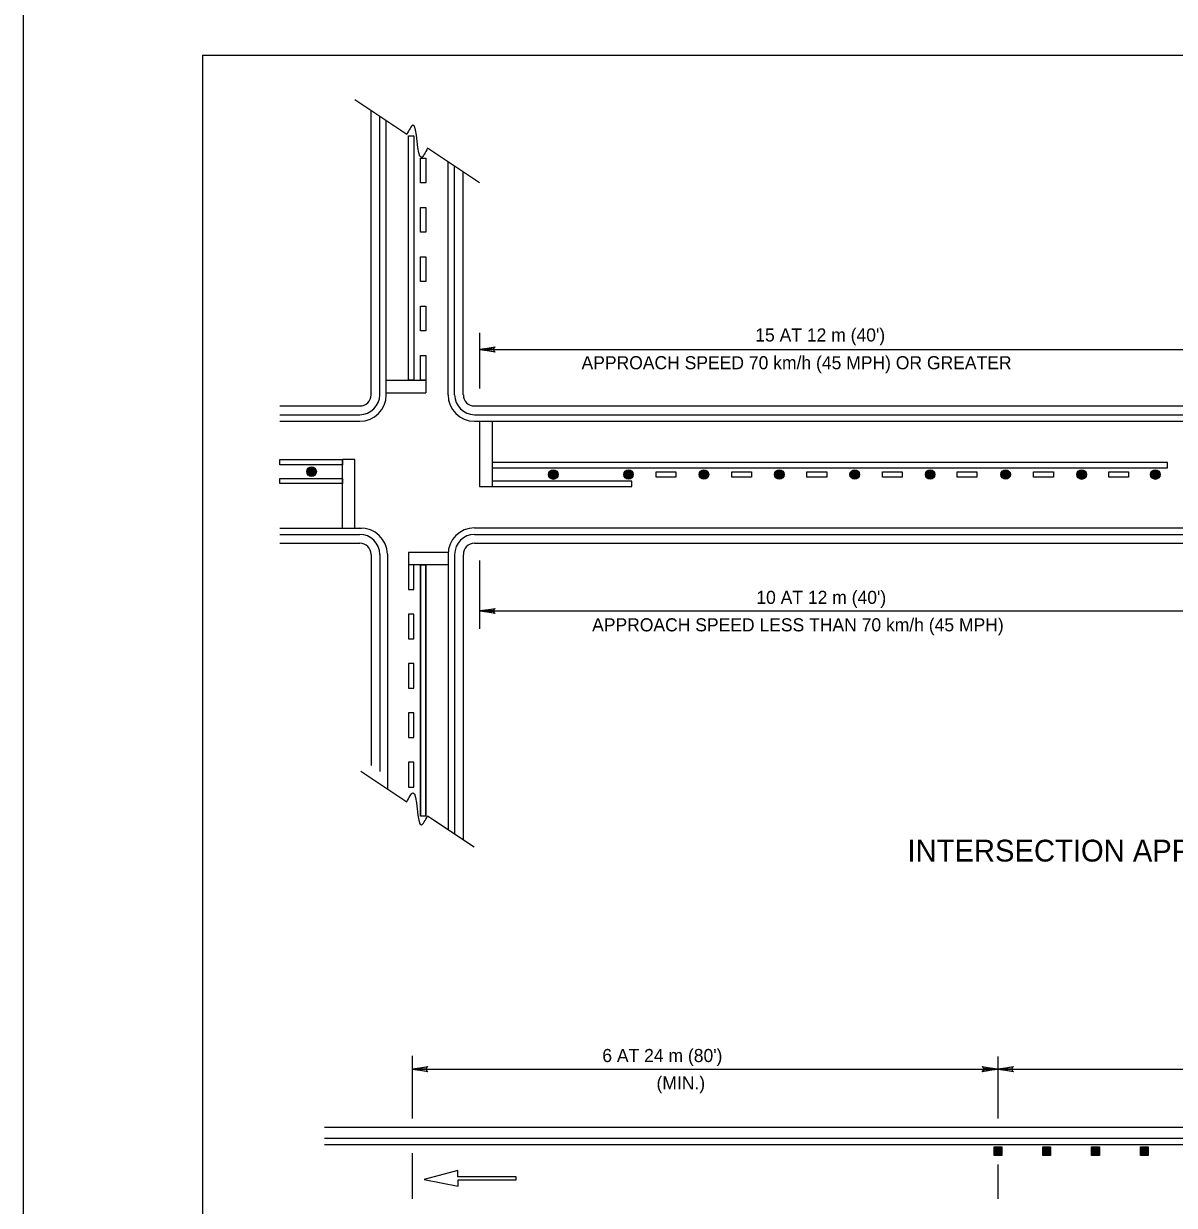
# Model space of a CAD drawing. Extents: x 639362 to 641108, y 298458 to 299646.
# Drawn here: x 639362.3 to 639626, y 298773.7 to 299044.4 of the extents above; entities that cross this region are included whole.
import ezdxf

# ---------------------------------------------------------------- set-up
doc = ezdxf.new("R2010")
doc.units = 0
for name, color, linetype in [('1', 7, 'Continuous'), ('2', 7, 'Continuous'), ('3', 7, 'Continuous'), ('PLT-BNDY', 7, 'Continuous')]:
    doc.layers.add(name, color=color, linetype=linetype)

# ---------------------------------------------------------------- blocks, each defined once
blk = doc.blocks.new('RARROW')
at = {"layer": '3'}
blk.add_lwpolyline([(-2.2695, 0.285), (-2.184875, 0.12075), (0, 0), (-2.2695, 0.285), (-2.38575, 0.384625), (0, 0), (-2.183125, -0.108), (-2.262875, -0.2705), (0, 0), (-2.38575, -0.379125), (-2.262875, -0.2705)], dxfattribs=at)

msp = doc.modelspace()

# ---------------------------------------------------------------- linework, layer by layer
at = {"layer": '1'}
for q in [(640189.27, 299037.19), (639403.27, 298473.19)]:
    msp.add_line((639403.27, 299037.19), q, dxfattribs=at)
at = {"layer": '2'}
for p, q in [((639450.1, 299019.03), (639438.22, 299026.95)), ((639441.9, 298959.38), (639441.9, 299024.5)), ((639443.9, 298959.38), (639443.9, 299023.16)), ((639445.4, 298959.38), (639445.4, 299022.16)), ((639450.51, 298962.69), (639450.51, 299018.73)), ((639450.51, 299018.73), (639451.71, 299018.73)), ((639451.71, 299018.73), (639451.71, 298962.69)), ((639466.76, 299007.92), (639454.86, 299015.86)), ((639459.55, 298959.38), (639459.55, 299012.73)), ((639461.05, 298959.38), (639461.05, 299011.73)), ((639463.05, 298959.38), (639463.05, 299010.4)), ((639466.77, 298973.53), (639466.77, 298960.81)), ((639466.77, 298969.77), (639638.59, 298969.77)), ((639445.4, 298962.69), (639454.45, 298962.69)), ((639451.71, 298962.69), (639450.51, 298962.69)), ((639454.45, 298962.7), (639454.45, 298959.83)), ((639445.4, 298959.83), (639454.45, 298959.83)), ((639421.03, 298956.81), (639439.33, 298956.81)), ((639421.03, 298954.81), (639439.33, 298954.81)), ((639465.63, 298956.81), (639777.38, 298956.81)), ((639465.63, 298954.81), (639777.38, 298954.81)), ((639421.03, 298953.31), (639439.33, 298953.31)), ((639465.63, 298953.31), (639777.38, 298953.31)), ((639466.78, 298953.31), (639466.78, 298938.35)), ((639469.64, 298953.31), (639469.64, 298938.35)), ((639438.18, 298944.52), (639435.33, 298944.52)), ((639435.33, 298928.83), (639435.33, 298944.52)), ((639438.18, 298928.83), (639438.18, 298944.52)), ((639624.41, 298943.86), (639469.63, 298943.86)), ((639469.63, 298943.86), (639469.63, 298942.66)), ((639624.41, 298942.66), (639624.41, 298943.86)), ((639469.63, 298942.66), (639624.41, 298942.66)), ((639466.78, 298938.35), (639469.64, 298938.35)), ((639501.67, 298939.55), (639469.64, 298939.55)), ((639469.64, 298939.55), (639469.64, 298938.35)), ((639469.64, 298938.35), (639501.67, 298938.35)), ((639501.67, 298938.35), (639501.67, 298939.55)), ((639421.03, 298928.83), (639439.69, 298928.83)), ((639421.03, 298927.38), (639439.33, 298927.38)), ((639465.63, 298928.88), (639777.38, 298928.88)), ((639465.63, 298927.38), (639777.38, 298927.38)), ((639421.03, 298925.38), (639439.33, 298925.38)), ((639465.63, 298925.38), (639777.38, 298925.38)), ((639441.9, 298922.81), (639441.9, 298874.4)), ((639443.9, 298922.81), (639443.9, 298873.07)), ((639445.69, 298922.83), (639445.69, 298869.02)), ((639450.51, 298923.24), (639450.51, 298920.39)), ((639459.57, 298923.24), (639450.51, 298923.24)), ((639459.55, 298922.81), (639459.55, 298859.78)), ((639461.05, 298922.81), (639461.05, 298858.78)), ((639463.05, 298922.81), (639463.05, 298857.44)), ((639459.55, 298920.39), (639450.51, 298920.39)), ((639454.45, 298920.39), (639453.25, 298920.39)), ((639453.25, 298920.39), (639453.25, 298862.84)), ((639453.25, 298862.84), (639453.25, 298920.39)), ((639453.25, 298920.39), (639454.45, 298920.39)), ((639454.45, 298862.84), (639454.45, 298920.39)), ((639454.45, 298920.39), (639454.45, 298862.84)), ((639466.77, 298921.38), (639466.77, 298905.73)), ((639466.77, 298909.84), (639638.59, 298909.84)), ((639439.54, 298873.12), (639450.1, 298866.08)), ((639454.45, 298862.84), (639453.25, 298862.84)), ((639454.86, 298862.91), (639465.53, 298855.8)), ((639451.32, 298807.88), (639451.32, 298793.58)), ((639585.52, 298807.8), (639585.52, 298793.58)), ((639451.32, 298804.88), (639585.52, 298804.88)), ((639585.52, 298804.88), (639797.99, 298804.88)), ((639431.25, 298791.58), (639952.64, 298791.58)), ((639431.25, 298789.08), (639952.64, 298789.08)), ((639431.25, 298787.58), (639952.64, 298787.58)), ((639584.64, 298787.09), (639586.41, 298787.09)), ((639584.64, 298785.05), (639584.64, 298787.09)), ((639584.81, 298786.92), (639586.23, 298786.92)), ((639584.81, 298785.23), (639584.81, 298786.92)), ((639584.99, 298786.74), (639586.06, 298786.74)), ((639584.99, 298785.41), (639584.99, 298786.74)), ((639585.17, 298785.59), (639585.17, 298786.56)), ((639585.17, 298786.56), (639585.88, 298786.56)), ((639585.88, 298786.56), (639585.88, 298785.59)), ((639586.06, 298786.74), (639586.06, 298785.41)), ((639586.23, 298786.92), (639586.23, 298785.23)), ((639586.41, 298787.09), (639586.41, 298785.05)), ((639595.82, 298787.09), (639597.59, 298787.09)), ((639595.82, 298785.05), (639595.82, 298787.09)), ((639596, 298786.92), (639597.42, 298786.92)), ((639596, 298785.23), (639596, 298786.92)), ((639596.17, 298786.74), (639597.24, 298786.74)), ((639596.17, 298785.41), (639596.17, 298786.74)), ((639596.35, 298785.59), (639596.35, 298786.56)), ((639596.35, 298786.56), (639597.06, 298786.56)), ((639597.06, 298786.56), (639597.06, 298785.59)), ((639597.24, 298786.74), (639597.24, 298785.41)), ((639597.42, 298786.92), (639597.42, 298785.23)), ((639597.59, 298787.09), (639597.59, 298785.05)), ((639607, 298787.09), (639608.78, 298787.09)), ((639607, 298785.05), (639607, 298787.09)), ((639607.18, 298786.92), (639608.6, 298786.92)), ((639607.18, 298785.23), (639607.18, 298786.92)), ((639607.36, 298786.74), (639608.42, 298786.74)), ((639607.36, 298785.41), (639607.36, 298786.74)), ((639607.54, 298785.59), (639607.54, 298786.56)), ((639607.54, 298786.56), (639608.24, 298786.56)), ((639608.24, 298786.56), (639608.24, 298785.59)), ((639608.42, 298786.74), (639608.42, 298785.41)), ((639608.6, 298786.92), (639608.6, 298785.23)), ((639608.78, 298787.09), (639608.78, 298785.05)), ((639618.19, 298787.09), (639619.96, 298787.09)), ((639618.19, 298785.05), (639618.19, 298787.09)), ((639618.36, 298786.92), (639619.78, 298786.92)), ((639618.36, 298785.23), (639618.36, 298786.92)), ((639618.54, 298786.74), (639619.61, 298786.74)), ((639618.54, 298785.41), (639618.54, 298786.74)), ((639618.72, 298785.59), (639618.72, 298786.56)), ((639618.72, 298786.56), (639619.43, 298786.56)), ((639619.43, 298786.56), (639619.43, 298785.59)), ((639619.61, 298786.74), (639619.61, 298785.41)), ((639619.78, 298786.92), (639619.78, 298785.23)), ((639619.96, 298787.09), (639619.96, 298785.05)), ((639451.32, 298785.58), (639451.32, 298775.16)), ((639586.41, 298785.05), (639584.64, 298785.05)), ((639586.23, 298785.23), (639584.81, 298785.23)), ((639586.06, 298785.41), (639584.99, 298785.41)), ((639585.88, 298785.59), (639585.17, 298785.59)), ((639585.35, 298786.39), (639585.7, 298786.39)), ((639585.35, 298785.76), (639585.35, 298786.39)), ((639585.7, 298785.76), (639585.35, 298785.76)), ((639585.52, 298786.21), (639585.52, 298785.94)), ((639585.7, 298786.39), (639585.7, 298785.76)), ((639597.59, 298785.05), (639595.82, 298785.05)), ((639597.42, 298785.23), (639596, 298785.23)), ((639597.24, 298785.41), (639596.17, 298785.41)), ((639597.06, 298785.59), (639596.35, 298785.59)), ((639596.53, 298786.39), (639596.88, 298786.39)), ((639596.53, 298785.76), (639596.53, 298786.39)), ((639596.88, 298785.76), (639596.53, 298785.76)), ((639596.7, 298786.21), (639596.7, 298785.94)), ((639596.88, 298786.39), (639596.88, 298785.76)), ((639608.78, 298785.05), (639607, 298785.05)), ((639608.6, 298785.23), (639607.18, 298785.23)), ((639608.42, 298785.41), (639607.36, 298785.41)), ((639608.24, 298785.59), (639607.54, 298785.59)), ((639607.71, 298786.39), (639608.07, 298786.39)), ((639607.71, 298785.76), (639607.71, 298786.39)), ((639608.07, 298785.76), (639607.71, 298785.76)), ((639607.89, 298786.21), (639607.89, 298785.94)), ((639608.07, 298786.39), (639608.07, 298785.76)), ((639619.96, 298785.05), (639618.19, 298785.05)), ((639619.78, 298785.23), (639618.36, 298785.23)), ((639619.61, 298785.41), (639618.54, 298785.41)), ((639619.43, 298785.59), (639618.72, 298785.59)), ((639618.9, 298786.39), (639619.25, 298786.39)), ((639618.9, 298785.76), (639618.9, 298786.39)), ((639619.25, 298785.76), (639618.9, 298785.76)), ((639619.07, 298786.21), (639619.07, 298785.94)), ((639619.25, 298786.39), (639619.25, 298785.76)), ((639461.79, 298781.66), (639454.07, 298779.55)), ((639461.79, 298780.22), (639461.79, 298781.66)), ((639585.52, 298783.05), (639585.52, 298775.16)), ((639454.07, 298779.55), (639461.87, 298778.07)), ((639475.12, 298780.22), (639461.79, 298780.22)), ((639461.87, 298778.07), (639461.87, 298779.51)), ((639461.87, 298779.51), (639475.12, 298779.51)), ((639475.12, 298779.51), (639475.12, 298780.22))]:
    msp.add_line(p, q, dxfattribs=at)
for points in [[(639453.25, 299013.56), (639454.45, 299013.56), (639454.45, 299007.91), (639453.25, 299007.91)], [(639453.25, 299002.26), (639454.45, 299002.26), (639454.45, 298996.6), (639453.25, 298996.6)], [(639453.25, 298990.95), (639454.45, 298990.95), (639454.45, 298985.3), (639453.25, 298985.3)], [(639453.25, 298979.65), (639454.45, 298979.65), (639454.45, 298973.99), (639453.25, 298973.99)], [(639453.25, 298968.34), (639454.45, 298968.34), (639454.45, 298962.69), (639453.25, 298962.69)], [(639421.03, 298944.52), (639435.33, 298944.52), (639435.33, 298943.32), (639421.03, 298943.32)], [(639507.23, 298941.72), (639511.75, 298941.72), (639511.75, 298940.52), (639507.23, 298940.52)], [(639524.56, 298941.72), (639529.08, 298941.72), (639529.08, 298940.52), (639524.56, 298940.52)], [(639541.79, 298941.72), (639546.31, 298941.72), (639546.31, 298940.52), (639541.79, 298940.52)], [(639559.06, 298941.72), (639563.58, 298941.72), (639563.58, 298940.52), (639559.06, 298940.52)], [(639576.2, 298941.72), (639580.72, 298941.72), (639580.72, 298940.52), (639576.2, 298940.52)], [(639593.72, 298941.72), (639598.24, 298941.72), (639598.24, 298940.52), (639593.72, 298940.52)], [(639610.93, 298941.72), (639615.45, 298941.72), (639615.45, 298940.52), (639610.93, 298940.52)], [(639421.03, 298940.21), (639435.33, 298940.21), (639435.33, 298939.01), (639421.03, 298939.01)], [(639450.51, 298914.73), (639451.71, 298914.73), (639451.71, 298920.39), (639450.51, 298920.39)], [(639450.51, 298903.43), (639451.71, 298903.43), (639451.71, 298909.08), (639450.51, 298909.08)], [(639450.51, 298892.12), (639451.71, 298892.12), (639451.71, 298897.78), (639450.51, 298897.78)], [(639450.51, 298880.82), (639451.71, 298880.82), (639451.71, 298886.47), (639450.51, 298886.47)], [(639450.51, 298869.51), (639451.71, 298869.51), (639451.71, 298875.17), (639450.51, 298875.17)]]:
    msp.add_lwpolyline(points, close=True, dxfattribs=at)
for centre, radius in [((639428.28, 298941.77), 1.1), ((639428.28, 298941.77), 1.02), ((639428.28, 298941.77), 0.946), ((639428.28, 298941.77), 0.868), ((639428.28, 298941.77), 0.789), ((639428.28, 298941.77), 0.711), ((639428.28, 298941.77), 0.633), ((639428.28, 298941.77), 0.554), ((639428.28, 298941.77), 0.476), ((639428.28, 298941.77), 0.398), ((639428.28, 298941.77), 0.32), ((639428.28, 298941.77), 0.241), ((639428.28, 298941.77), 0.163), ((639428.28, 298941.77), 0.0846), ((639483.68, 298941.1), 1.1), ((639483.68, 298941.1), 1.02), ((639483.68, 298941.1), 0.946), ((639483.68, 298941.1), 0.868), ((639483.68, 298941.1), 0.789), ((639483.68, 298941.1), 0.711), ((639483.68, 298941.1), 0.633), ((639483.68, 298941.1), 0.554), ((639483.68, 298941.1), 0.476), ((639483.68, 298941.1), 0.398), ((639483.68, 298941.1), 0.32), ((639483.68, 298941.1), 0.241), ((639483.68, 298941.1), 0.163), ((639483.68, 298941.1), 0.0846), ((639500.89, 298941.11), 1.1), ((639500.89, 298941.11), 1.02), ((639500.89, 298941.11), 0.946), ((639500.89, 298941.11), 0.868), ((639500.89, 298941.11), 0.789), ((639500.89, 298941.11), 0.711), ((639500.89, 298941.11), 0.633), ((639500.89, 298941.11), 0.554), ((639500.89, 298941.11), 0.476), ((639500.89, 298941.11), 0.398), ((639500.89, 298941.11), 0.32), ((639500.89, 298941.11), 0.241), ((639500.89, 298941.11), 0.163), ((639500.89, 298941.11), 0.0846), ((639518.17, 298941.11), 1.1), ((639518.17, 298941.11), 1.02), ((639518.17, 298941.11), 0.946), ((639518.17, 298941.11), 0.868), ((639518.17, 298941.11), 0.789), ((639518.17, 298941.11), 0.711), ((639518.17, 298941.11), 0.633), ((639518.17, 298941.11), 0.554), ((639518.17, 298941.11), 0.476), ((639518.17, 298941.11), 0.398), ((639518.17, 298941.11), 0.32), ((639518.17, 298941.11), 0.241), ((639518.17, 298941.11), 0.163), ((639518.17, 298941.11), 0.0846), ((639535.45, 298941.11), 1.1), ((639535.45, 298941.11), 1.02), ((639535.45, 298941.11), 0.946), ((639535.45, 298941.11), 0.868), ((639535.45, 298941.11), 0.789), ((639535.45, 298941.11), 0.711), ((639535.45, 298941.11), 0.633), ((639535.45, 298941.11), 0.554), ((639535.45, 298941.11), 0.476), ((639535.45, 298941.11), 0.398), ((639535.45, 298941.11), 0.32), ((639535.45, 298941.11), 0.241), ((639535.45, 298941.11), 0.163), ((639535.45, 298941.11), 0.0846), ((639552.73, 298941.11), 1.1), ((639552.73, 298941.11), 1.02), ((639552.73, 298941.11), 0.946), ((639552.73, 298941.11), 0.868), ((639552.73, 298941.11), 0.789), ((639552.73, 298941.11), 0.711), ((639552.73, 298941.11), 0.633), ((639552.73, 298941.11), 0.554), ((639552.73, 298941.11), 0.476), ((639552.73, 298941.11), 0.398), ((639552.73, 298941.11), 0.32), ((639552.73, 298941.11), 0.241), ((639552.73, 298941.11), 0.163), ((639552.73, 298941.11), 0.0846), ((639570.01, 298941.11), 1.1), ((639570.01, 298941.11), 1.02), ((639570.01, 298941.11), 0.946), ((639570.01, 298941.11), 0.868), ((639570.01, 298941.11), 0.789), ((639570.01, 298941.11), 0.711), ((639570.01, 298941.11), 0.633), ((639570.01, 298941.11), 0.554), ((639570.01, 298941.11), 0.476), ((639570.01, 298941.11), 0.398), ((639570.01, 298941.11), 0.32), ((639570.01, 298941.11), 0.241), ((639570.01, 298941.11), 0.163), ((639570.01, 298941.11), 0.0846), ((639587.29, 298941.11), 1.1), ((639587.29, 298941.11), 1.02), ((639587.29, 298941.11), 0.946), ((639587.29, 298941.11), 0.868), ((639587.29, 298941.11), 0.789), ((639587.29, 298941.11), 0.711), ((639587.29, 298941.11), 0.633), ((639587.29, 298941.11), 0.554), ((639587.29, 298941.11), 0.476), ((639587.29, 298941.11), 0.398), ((639587.29, 298941.11), 0.32), ((639587.29, 298941.11), 0.241), ((639587.29, 298941.11), 0.163), ((639587.29, 298941.11), 0.0846), ((639604.71, 298941.1), 1.1), ((639604.71, 298941.1), 1.02), ((639604.71, 298941.1), 0.946), ((639604.71, 298941.1), 0.868), ((639604.71, 298941.1), 0.789), ((639604.71, 298941.1), 0.711), ((639604.71, 298941.1), 0.633), ((639604.71, 298941.1), 0.554), ((639604.71, 298941.1), 0.476), ((639604.71, 298941.1), 0.398), ((639604.71, 298941.1), 0.32), ((639604.71, 298941.1), 0.241), ((639604.71, 298941.1), 0.163), ((639604.71, 298941.1), 0.0846), ((639621.61, 298941.1), 1.1), ((639621.61, 298941.1), 1.02), ((639621.61, 298941.1), 0.946), ((639621.61, 298941.1), 0.868), ((639621.61, 298941.1), 0.789), ((639621.61, 298941.1), 0.711), ((639621.61, 298941.1), 0.633), ((639621.61, 298941.1), 0.554), ((639621.61, 298941.1), 0.476), ((639621.61, 298941.1), 0.398), ((639621.61, 298941.1), 0.32), ((639621.61, 298941.1), 0.241), ((639621.61, 298941.1), 0.163), ((639621.61, 298941.1), 0.0846)]:
    msp.add_circle(centre, radius, dxfattribs=at)
for centre, radius, start, end in [((639439.33, 298959.38), 4.57, 270, 0), ((639439.33, 298959.38), 6.07, 270, 0), ((639439.33, 298959.38), 2.57, 270, 0), ((639465.63, 298959.38), 6.07, 180, 270), ((639465.63, 298959.38), 4.57, 180, 270), ((639465.63, 298959.38), 2.57, 180, 270), ((639439.51, 298922.65), 6.18, 1.6739, 91.6739), ((639439.33, 298922.81), 4.57, 0, 90), ((639465.63, 298922.81), 6.07, 90, 180), ((639465.63, 298922.81), 4.57, 90, 180), ((639439.33, 298922.81), 2.57, 0, 90), ((639465.63, 298922.81), 2.57, 90, 180)]:
    msp.add_arc(centre, radius, start, end, dxfattribs=at)
for points in [[(639454.86, 299015.86), (639453.46, 299013.77), (639451.49, 299021.12), (639450.1, 299019.03)], [(639450.1, 298866.08), (639451.49, 298868.17), (639453.47, 298860.82), (639454.86, 298862.91)]]:
    msp.add_spline(points, degree=3, dxfattribs=at)
at = {"layer": 'PLT-BNDY'}
msp.add_lwpolyline([(639362.31, 299051.63), (640203.31, 299051.63), (640203.31, 298457.63), (639362.31, 298457.63)], close=True, dxfattribs=at)

# ---------------------------------------------------------------- block references
at = {"layer": '2', "xscale": 1.5089217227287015, "yscale": 1.5711553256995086, "rotation": 180}
for p in [(639466.77, 298969.77), (639466.77, 298909.84), (639451.32, 298804.88), (639585.52, 298804.88)]:
    msp.add_blockref('RARROW', p, dxfattribs=at)
at = {"layer": '2', "xscale": 1.5089217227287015, "yscale": 1.5711553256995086}
msp.add_blockref('RARROW', (639585.52, 298804.88), dxfattribs=at)

# ---------------------------------------------------------------- texts
at = {"layer": '2'}
for s, height, p in [("15 AT 12 m (40')", 3, (639529.94, 298971.58)), ('APPROACH SPEED 70 km/h (45 MPH) OR GREATER', 3, (639490.13, 298965.22)), ("10 AT 12 m (40')", 3, (639530.18, 298911.46)), ('APPROACH SPEED LESS THAN 70 km/h (45 MPH)', 3, (639492.56, 298905.17)), ('INTERSECTION APPROACH', 5, (639564.81, 298852.43)), ("6 AT 24 m (80')", 3, (639494.89, 298806.49)), ('(MIN.)', 3, (639507.31, 298800.22))]:
    msp.add_text(s, height=height, dxfattribs=at).set_placement(p)

doc.saveas('drawing.dxf')
